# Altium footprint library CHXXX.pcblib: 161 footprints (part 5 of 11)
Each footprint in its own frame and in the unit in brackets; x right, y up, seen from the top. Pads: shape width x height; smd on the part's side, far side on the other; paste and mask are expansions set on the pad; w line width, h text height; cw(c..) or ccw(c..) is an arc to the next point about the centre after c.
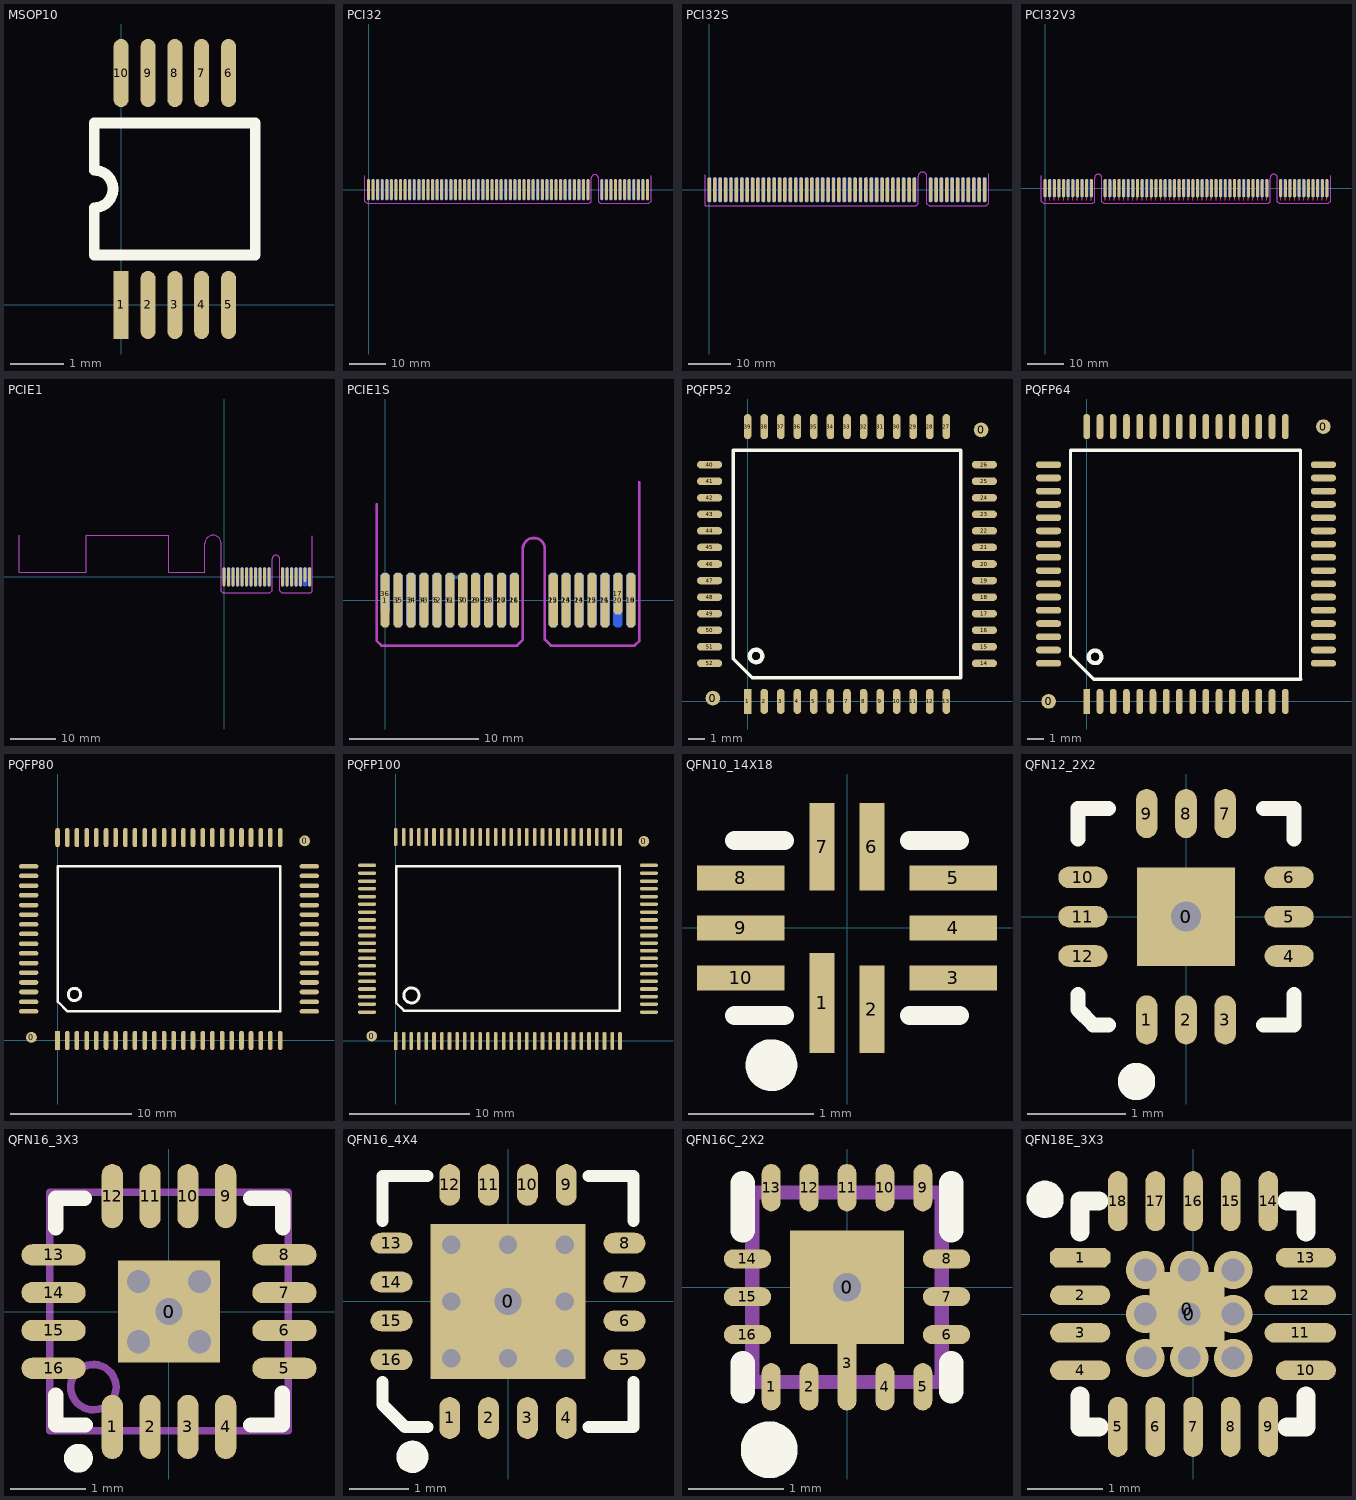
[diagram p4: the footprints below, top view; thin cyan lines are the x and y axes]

## MSOP10 [mil]
pads (10):
  rect 11x50 smd mask+2: 1(0,0)
  oval 11x50 smd mask+2: 2(19.68,0) 3(39.37,0) 4(59.06,0) 5(78.74,0) 6(78.74,170) 7(59.06,170) 8(39.37,170) 9(19.68,170) 10(0,170)
TopOverlay:
  lines w7.87: -19.8,36.65 98.32,36.65 98.32,133.35 -19.8,133.35 -19.8,98.78 cw(c-19.8,85) -19.8,71.22 -19.8,36.65

## PCI32 [mil]
pads (120):
  oct 32x230 smd: 1(0,0) 2(50,0) 3(100,0) 4(150,0) 5(200,0) 6(250,0) 7(300,0) 8(350,0) 9(400,0) 10(450,0) 11(500,0) 12(550,0) 13(600,0) 14(650,0) 15(700,0) 16(750,0) 17(800,0) 18(850,0) 19(900,0) 20(950,0) 21(1000,0) 22(1050,0) 23(1100,0) 24(1150,0) 25(1200,0) 26(1250,0) 27(1300,0) 28(1350,0) 29(1400,0) 30(1450,0) 31(1500,0) 32(1550,0) 33(1600,0) 34(1650,0) 35(1700,0) 36(1750,0) 37(1800,0) 38(1850,0) 39(1900,0) 40(1950,0) 41(2000,0) 42(2050,0) 43(2100,0) 44(2150,0) 45(2200,0) 46(2250,0) 47(2300,0) 48(2350,0) 49(2400,0) 52(2550,0) 53(2600,0) 54(2650,0) 55(2700,0) 56(2750,0) 57(2800,0) 58(2850,0) 59(2900,0) 60(2950,0) 61(3000,0) 62(3050,0)
  oct 32x230 smd far side: 63(3050,0) 64(3000,0) 65(2950,0) 66(2900,0) 67(2850,0) 68(2800,0) 69(2750,0) 70(2700,0) 71(2650,0) 72(2600,0) 73(2550,0) 76(2400,0) 77(2350,0) 78(2300,0) 79(2250,0) 80(2200,0) 81(2150,0) 82(2100,0) 83(2050,0) 84(2000,0) 85(1950,0) 86(1900,0) 87(1850,0) 88(1800,0) 89(1750,0) 90(1700,0) 91(1650,0) 92(1600,0) 93(1550,0) 94(1500,0) 95(1450,0) 96(1400,0) 97(1350,0) 98(1300,0) 99(1250,0) 100(1200,0) 101(1150,0) 102(1100,0) 103(1050,0) 104(1000,0) 105(950,0) 106(900,0) 107(850,0) 108(800,0) 109(750,0) 110(700,0) 111(650,0) 112(600,0) 113(550,0) 114(500,0) 115(450,0) 116(400,0) 117(350,0) 118(300,0) 119(250,0) 120(200,0) 121(150,0) 122(100,0) 123(50,0) 124(0,0)
TopSolder:
  rectangle: -40,-150 2435,120
  rectangle: 2515,-150 3090,120
BottomSolder:
  rectangle: 2515,-150 3090,120
  rectangle: -40,-150 2435,120
KeepOutLayer:
  lines w10: -40,150 -40,-125 -15,-150 2415,-150 2435,-130 2435,125 cw(c2475,125) 2515,125 2515,-130 2535,-150 3065,-150 3090,-125 3090,150
Mechanical1:
  lines w10: -40,150 -40,-125 -15,-150 2415,-150 2435,-130 2435,125 cw(c2475,125) 2515,125 2515,-130 2535,-150 3065,-150 3090,-125 3090,150

## PCI32S [mil]
pads (100):
  oct 32x230 smd: 11(0,0) 12(50,0) 13(100,0) 14(150,0) 15(200,0) 16(250,0) 17(300,0) 18(350,0) 19(400,0) 20(450,0) 21(500,0) 22(550,0) 23(600,0) 24(650,0) 25(700,0) 26(750,0) 27(800,0) 28(850,0) 29(900,0) 30(950,0) 31(1000,0) 32(1050,0) 33(1100,0) 34(1150,0) 35(1200,0) 36(1250,0) 37(1300,0) 38(1350,0) 39(1400,0) 40(1450,0) 41(1500,0) 42(1550,0) 43(1600,0) 44(1650,0) 45(1700,0) 46(1750,0) 47(1800,0) 48(1850,0) 49(1900,0) 52(2050,0) 53(2100,0) 54(2150,0) 55(2200,0) 56(2250,0) 57(2300,0) 58(2350,0) 59(2400,0) 60(2450,0) 61(2500,0) 62(2550,0)
  oct 32x230 smd far side: 63(2550,0) 64(2500,0) 65(2450,0) 66(2400,0) 67(2350,0) 68(2300,0) 69(2250,0) 70(2200,0) 71(2150,0) 72(2100,0) 73(2050,0) 76(1900,0) 77(1850,0) 78(1800,0) 79(1750,0) 80(1700,0) 81(1650,0) 82(1600,0) 83(1550,0) 84(1500,0) 85(1450,0) 86(1400,0) 87(1350,0) 88(1300,0) 89(1250,0) 90(1200,0) 91(1150,0) 92(1100,0) 93(1050,0) 94(1000,0) 95(950,0) 96(900,0) 97(850,0) 98(800,0) 99(750,0) 100(700,0) 101(650,0) 102(600,0) 103(550,0) 104(500,0) 105(450,0) 106(400,0) 107(350,0) 108(300,0) 109(250,0) 110(200,0) 111(150,0) 112(100,0) 113(50,0) 114(0,0)
TopSolder:
  rectangle: -40,-150 1935,120
  rectangle: 2015,-150 2590,120
BottomSolder:
  rectangle: 2015,-150 2590,120
  rectangle: -40,-150 1935,120
KeepOutLayer:
  lines w10: -40,140 -40,-150 1915,-150 1935,-130 1935,125 cw(c1975,125) 2015,125 2015,-130 2035,-150 2565,-150 2590,-125 2590,150
Mechanical1:
  lines w10: -40,140 -40,-150 1915,-150 1935,-130 1935,125 cw(c1975,125) 2015,125 2015,-130 2035,-150 2565,-150 2590,-125 2590,150

## PCI32V3 [mm]
pads (116):
  oval 0.813x5 smd: 1(0,0) 2(1.27,0) 3(2.54,0) 4(3.81,0) 5(5.08,0) 6(6.35,0) 7(7.62,0) 8(8.89,0) 9(10.16,0) 10(11.43,0) 11(12.7,0) 14(16.51,0) 15(17.78,0) 16(19.05,0) 17(20.32,0) 18(21.59,0) 19(22.86,0) 20(24.13,0) 21(25.4,0) 22(26.67,0) 23(27.94,0) 24(29.21,0) 25(30.48,0) 26(31.75,0) 27(33.02,0) 28(34.29,0) 29(35.56,0) 30(36.83,0) 31(38.1,0) 32(39.37,0) 33(40.64,0) 34(41.91,0) 35(43.18,0) 36(44.45,0) 37(45.72,0) 38(46.99,0) 39(48.26,0) 40(49.53,0) 41(50.8,0) 42(52.07,0) 43(53.34,0) 44(54.61,0) 45(55.88,0) 46(57.15,0) 47(58.42,0) 48(59.69,0) 49(60.96,0) 52(64.77,0) 53(66.04,0) 54(67.31,0) 55(68.58,0) 56(69.85,0) 57(71.12,0) 58(72.39,0) 59(73.66,0) 60(74.93,0) 61(76.2,0) 62(77.47,0)
  oval 0.813x5 smd far side: 63(77.47,0) 64(76.2,0) 65(74.93,0) 66(73.66,0) 67(72.39,0) 68(71.12,0) 69(69.85,0) 70(68.58,0) 71(67.31,0) 72(66.04,0) 73(64.77,0) 76(60.96,0) 77(59.69,0) 78(58.42,0) 79(57.15,0) 80(55.88,0) 81(54.61,0) 82(53.34,0) 83(52.07,0) 84(50.8,0) 85(49.53,0) 86(48.26,0) 87(46.99,0) 88(45.72,0) 89(44.45,0) 90(43.18,0) 91(41.91,0) 92(40.64,0) 93(39.37,0) 94(38.1,0) 95(36.83,0) 96(35.56,0) 97(34.29,0) 98(33.02,0) 99(31.75,0) 100(30.48,0) 101(29.21,0) 102(27.94,0) 103(26.67,0) 104(25.4,0) 105(24.13,0) 106(22.86,0) 107(21.59,0) 108(20.32,0) 109(19.05,0) 110(17.78,0) 111(16.51,0) 114(12.7,0) 115(11.43,0) 116(10.16,0) 117(8.89,0) 118(7.62,0) 119(6.35,0) 120(5.08,0) 121(3.81,0) 122(2.54,0) 123(1.27,0) 124(0,0)
TopLayer:
  lines w0.305: 0,-3.302 0,-2 ; 1.27,-3.302 1.27,-2 ; 2.54,-3.302 2.54,-2 ; 3.81,-3.302 3.81,-2 ; 5.08,-3.302 5.08,-2 ; 6.35,-3.302 6.35,-2 ; 7.62,-3.302 7.62,-2 ; 8.89,-3.302 8.89,-2 ; 10.16,-3.302 10.16,-2 ; 11.43,-3.302 11.43,-2 ; 12.7,-3.302 12.7,-2 ; 16.51,-3.302 16.51,-2 ; 17.78,-3.302 17.78,-2 ; 19.05,-3.302 19.05,-2 ; 20.32,-3.302 20.32,-2 ; 21.59,-3.302 21.59,-2 ; 22.86,-3.302 22.86,-2 ; 24.13,-3.302 24.13,-2 ; 25.4,-3.302 25.4,-2 ; 26.67,-3.302 26.67,-2 ; 27.94,-3.302 27.94,-2 ; 29.21,-3.302 29.21,-2 ; 30.48,-3.302 30.48,-2 ; 31.75,-3.302 31.75,-2 ; 33.02,-3.302 33.02,-2 ; 34.29,-3.302 34.29,-2 ; 35.56,-3.302 35.56,-2 ; 36.83,-3.302 36.83,-2 ; 38.1,-3.302 38.1,-2 ; 39.37,-3.302 39.37,-2 ; 40.64,-3.302 40.64,-2 ; 41.91,-3.302 41.91,-2 ; 43.18,-3.302 43.18,-2 ; 44.45,-3.302 44.45,-2 ; 45.72,-3.302 45.72,-2 ; 46.99,-3.302 46.99,-2 ; 48.26,-3.302 48.26,-2 ; 49.53,-3.302 49.53,-2 ; 50.8,-3.302 50.8,-2 ; 52.07,-3.302 52.07,-2 ; 53.34,-3.302 53.34,-2 ; 54.61,-3.302 54.61,-2 ; 55.88,-3.302 55.88,-2 ; 57.15,-3.302 57.15,-2 ; 58.42,-3.302 58.42,-2 ; 59.69,-3.302 59.69,-2 ; 60.96,-3.302 60.96,-2 ; 64.77,-3.302 64.77,-2 ; 66.04,-3.302 66.04,-2 ; 67.31,-3.302 67.31,-2 ; 68.58,-3.302 68.58,-2 ; 69.85,-3.302 69.85,-2 ; 71.12,-3.302 71.12,-2 ; 72.39,-3.302 72.39,-2 ; 73.66,-3.302 73.66,-2 ; 74.93,-3.302 74.93,-2 ; 76.2,-3.302 76.2,-2 ; 77.47,-3.302 77.47,-2
BottomLayer:
  lines w0.305: 0,-3.302 0,-2 ; 1.27,-3.302 1.27,-2 ; 2.54,-3.302 2.54,-2 ; 3.81,-3.302 3.81,-2 ; 5.08,-3.302 5.08,-2 ; 6.35,-3.302 6.35,-2 ; 7.62,-3.302 7.62,-2 ; 8.89,-3.302 8.89,-2 ; 10.16,-3.302 10.16,-2 ; 11.43,-3.302 11.43,-2 ; 12.7,-3.302 12.7,-2 ; 16.51,-3.302 16.51,-2 ; 17.78,-3.302 17.78,-2 ; 19.05,-3.302 19.05,-2 ; 20.32,-3.302 20.32,-2 ; 21.59,-3.302 21.59,-2 ; 22.86,-3.302 22.86,-2 ; 24.13,-3.302 24.13,-2 ; 25.4,-3.302 25.4,-2 ; 26.67,-3.302 26.67,-2 ; 27.94,-3.302 27.94,-2 ; 29.21,-3.302 29.21,-2 ; 30.48,-3.302 30.48,-2 ; 31.75,-3.302 31.75,-2 ; 33.02,-3.302 33.02,-2 ; 34.29,-3.302 34.29,-2 ; 35.56,-3.302 35.56,-2 ; 36.83,-3.302 36.83,-2 ; 38.1,-3.302 38.1,-2 ; 39.37,-3.302 39.37,-2 ; 40.64,-3.302 40.64,-2 ; 41.91,-3.302 41.91,-2 ; 43.18,-3.302 43.18,-2 ; 44.45,-3.302 44.45,-2 ; 45.72,-3.302 45.72,-2 ; 46.99,-3.302 46.99,-2 ; 48.26,-3.302 48.26,-2 ; 49.53,-3.302 49.53,-2 ; 50.8,-3.302 50.8,-2 ; 52.07,-3.302 52.07,-2 ; 53.34,-3.302 53.34,-2 ; 54.61,-3.302 54.61,-2 ; 55.88,-3.302 55.88,-2 ; 57.15,-3.302 57.15,-2 ; 58.42,-3.302 58.42,-2 ; 59.69,-3.302 59.69,-2 ; 60.96,-3.302 60.96,-2 ; 64.77,-3.302 64.77,-2 ; 66.04,-3.302 66.04,-2 ; 67.31,-3.302 67.31,-2 ; 68.58,-3.302 68.58,-2 ; 69.85,-3.302 69.85,-2 ; 71.12,-3.302 71.12,-2 ; 72.39,-3.302 72.39,-2 ; 73.66,-3.302 73.66,-2 ; 74.93,-3.302 74.93,-2 ; 76.2,-3.302 76.2,-2 ; 77.47,-3.302 77.47,-2
TopSolder:
  rectangle: 63.881,-4.039 78.283,2.794
  region: 61.849,2.794 15.621,2.794 15.621,-3.962 61.849,-3.962
  rectangle: -1.016,-4.064 13.386,2.769
BottomSolder:
  rectangle: 15.621,-4.267 61.849,2.794
  rectangle: 63.881,-4.115 78.257,2.692
  rectangle: -0.991,-4.089 13.386,2.718
KeepOutLayer:
  lines w0.254: -1.016,3.429 -1.016,-3.556 -0.381,-4.191 13.081,-4.191 13.589,-3.683 13.589,2.794 cw(c14.605,2.794) 15.621,2.794 15.621,-3.683 16.129,-4.191 61.341,-4.191 61.849,-3.683 61.849,2.794 cw(c62.865,2.794) 63.881,2.794 63.881,-3.683 64.389,-4.191 77.851,-4.191 78.486,-3.556 78.486,3.429
Mechanical1:
  lines w0.254: -1.016,3.429 -1.016,-3.556 -0.381,-4.191 13.081,-4.191 13.589,-3.683 13.589,2.794 cw(c14.605,2.794) 15.621,2.794 15.621,-3.683 16.129,-4.191 61.341,-4.191 61.849,-3.683 61.849,2.794 cw(c62.865,2.794) 63.881,2.794 63.881,-3.683 64.389,-4.191 77.851,-4.191 78.486,-3.556 78.486,3.429

## PCIE1 [mm]
pads (36):
  oct 0.7x4.2 smd: 1(0,0) 2(1,0) 3(2,0) 4(3,0) 5(4,0) 6(5,0) 7(6,0) 8(7,0) 9(8,0) 10(9,0) 11(10,0) 12(13,0) 13(14,0) 14(15,0) 15(16,0) 16(17,0) 18(19,0)
  oct 0.7x3.2 smd: 17(18,0.5)
  oct 0.7x4.2 smd far side: 19(19,0) 20(18,0) 21(17,0) 22(16,0) 23(15,0) 24(14,0) 25(13,0) 26(10,0) 27(9,0) 28(8,0) 29(7,0) 30(6,0) 31(5,0) 32(4,0) 33(3,0) 34(2,0) 35(1,0)
  oct 0.7x3.2 smd far side: 36(0,0.5)
KeepOutLayer:
  lines w0.2: -45.644,9.233 -45.644,0.983 -30.644,0.983 -30.644,9.233 -12.3,9.233 -12.3,0.983 -4.3,0.983 -4.3,7.414 cw(c-2.475,7.414) -0.65,7.414 -0.65,-3.149 -0.294,-3.504 ; -0.288,-3.517 10.194,-3.517 ; 10.194,-3.504 10.652,-3.047 10.652,3.988 ; 10.649,3.953 cw(c11.5,3.953) 12.351,3.953 ; 12.348,3.988 12.348,-3.045 12.806,-3.502 ; 12.808,-3.517 19.294,-3.517 ; 19.294,-3.504 19.65,-3.149 19.65,9.101
Mechanical1:
  lines w0.2: -45.644,9.233 -45.644,0.983 -30.644,0.983 -30.644,9.233 -12.3,9.233 -12.3,0.983 -4.3,0.983 -4.3,7.414 ; 10.649,3.953 10.649,-3.045 10.652,-3.047 10.188,-3.511 -0.288,-3.511 -0.65,-3.149 -0.65,7.414 ccw(c-2.475,7.414) -4.3,7.414 ; 10.652,3.988 cw(c11.5,3.953) 12.349,3.953 ; 12.351,3.953 12.351,-3.042 12.808,-3.499 19.277,-3.499 19.628,-3.149 19.628,9.079 ; -4.3,7.414 -4.3,7.414

## PCIE1S [mm]
pads (36):
  oct 0.7x4.2 smd: 1(0,0) 2(1,0) 3(2,0) 4(3,0) 5(4,0) 6(5,0) 7(6,0) 8(7,0) 9(8,0) 10(9,0) 11(10,0) 12(13,0) 13(14,0) 14(15,0) 15(16,0) 16(17,0) 18(19,0)
  oct 0.7x3.2 smd: 17(18,0.5)
  oct 0.7x4.2 smd far side: 19(19,0) 20(18,0) 21(17,0) 22(16,0) 23(15,0) 24(14,0) 25(13,0) 26(10,0) 27(9,0) 28(8,0) 29(7,0) 30(6,0) 31(5,0) 32(4,0) 33(3,0) 34(2,0) 35(1,0)
  oct 0.7x3.2 smd far side: 36(0,0.5)
BottomLayer:
  lines w0.254: 5.08,1.778 5.842,1.778
KeepOutLayer:
  lines w0.2: -0.65,7.414 -0.65,-3.149 -0.294,-3.504 ; -0.288,-3.517 10.194,-3.517 ; 10.194,-3.504 10.652,-3.047 10.652,3.988 ; 10.649,3.953 cw(c11.5,3.953) 12.351,3.953 ; 12.348,3.988 12.348,-3.045 12.821,-3.517 19.294,-3.517 ; 19.294,-3.504 19.65,-3.149 19.65,9.101
Mechanical1:
  lines w0.2: -0.65,7.414 -0.65,-3.149 -0.65,-3.155 -0.288,-3.517 10.194,-3.517 10.652,-3.06 10.652,3.953 cw(c11.5,3.953) 12.349,3.953 ; 12.348,-3.045 12.353,-3.045 12.826,-3.517 19.294,-3.517 19.65,-3.161 19.65,-3.149 19.65,9.101 ; 12.351,-3.042 12.351,3.953

## PQFP52 [mil]
pads (54):
  round 35 smd: 0(-82.68,7.87) 0(555.12,645.67)
  rect 18x60 smd: 1(0,0)
  oval 18x60 smd: 2(39.37,0) 3(78.74,0) 4(118.11,0) 5(157.48,0) 6(196.85,0) 7(236.22,0) 8(275.59,0) 9(314.96,0) 10(354.33,0) 11(393.7,0) 12(433.07,0) 13(472.44,0) 27(472.44,653.54) 28(433.07,653.54) 29(393.7,653.54) 30(354.33,653.54) 31(314.96,653.54) 32(275.59,653.54) 33(236.22,653.54) 34(196.85,653.54) 35(157.48,653.54) 36(118.11,653.54) 37(78.74,653.54) 38(39.37,653.54) 39(0,653.54)
  oval 60x18 smd: 14(562.99,90.55) 15(562.99,129.92) 16(562.99,169.29) 17(562.99,208.66) 18(562.99,248.03) 19(562.99,287.4) 20(562.99,326.77) 21(562.99,366.14) 22(562.99,405.51) 23(562.99,444.88) 24(562.99,484.25) 25(562.99,523.62) 26(562.99,562.99) 40(-90.55,562.99) 41(-90.55,523.62) 42(-90.55,484.25) 43(-90.55,444.88) 44(-90.55,405.51) 45(-90.55,366.14) 46(-90.55,326.77) 47(-90.55,287.4) 48(-90.55,248.03) 49(-90.55,208.66) 50(-90.55,169.29) 51(-90.55,129.92) 52(-90.55,90.55)
TopOverlay:
  circle w10: c20,108 r15
  lines w7.87: -34.06,101.18 -34.06,597.05 506.5,597.05 506.5,56.5 10.63,56.5 -34.06,101.18

## PQFP64 [mil]
pads (66):
  round 35 smd: 0(-90.55,0) 0(562.99,653.54)
  rect 16x60 smd: 1(0,0)
  oval 16x60 smd: 2(31.5,0) 3(62.99,0) 4(94.49,0) 5(125.98,0) 6(157.48,0) 7(188.98,0) 8(220.47,0) 9(251.97,0) 10(283.46,0) 11(314.96,0) 12(346.46,0) 13(377.95,0) 14(409.45,0) 15(440.94,0) 16(472.44,0) 33(472.44,653.54) 34(440.94,653.54) 35(409.45,653.54) 36(377.95,653.54) 37(346.46,653.54) 38(314.96,653.54) 39(283.46,653.54) 40(251.97,653.54) 41(220.47,653.54) 42(188.98,653.54) 43(157.48,653.54) 44(125.98,653.54) 45(94.49,653.54) 46(62.99,653.54) 47(31.5,653.54) 48(0,653.54)
  oval 60x16 smd: 17(562.99,90.55) 18(562.99,122.05) 19(562.99,153.54) 20(562.99,185.04) 21(562.99,216.54) 22(562.99,248.03) 23(562.99,279.53) 24(562.99,311.02) 25(562.99,342.52) 26(562.99,374.02) 27(562.99,405.51) 28(562.99,437.01) 29(562.99,468.5) 30(562.99,500) 31(562.99,531.5) 32(562.99,562.99) 49(-90.55,562.99) 50(-90.55,531.5) 51(-90.55,500) 52(-90.55,468.5) 53(-90.55,437.01) 54(-90.55,405.51) 55(-90.55,374.02) 56(-90.55,342.52) 57(-90.55,311.02) 58(-90.55,279.53) 59(-90.55,248.03) 60(-90.55,216.54) 61(-90.55,185.04) 62(-90.55,153.54) 63(-90.55,122.05) 64(-90.55,90.55)
TopOverlay:
  circle w10: c20,106 r15
  lines w7.87: -38.34,107.06 -38.34,597.65 508.78,597.65 508.78,52.53
  lines w8: -38.34,107.06 -38.05,107.06 16.47,52.53 508.78,52.53

## PQFP80 [mil]
pads (82):
  round 35 smd: 0(-85,10) 0(805,650)
  rect 15x63 smd: 1(0,0)
  oval 15x63 smd: 2(32,0) 3(63,0) 4(95,0) 5(126,0) 6(158,0) 7(189,0) 8(221,0) 9(252,0) 10(284,0) 11(315,0) 12(347,0) 13(378,0) 14(410,0) 15(441,0) 16(473,0) 17(504,0) 18(536,0) 19(567,0) 20(599,0) 21(630,0) 22(662,0) 23(693,0) 24(725,0) 41(725,661) 42(693,661) 43(662,661) 44(630,661) 45(599,661) 46(567,661) 47(536,661) 48(504,661) 49(473,661) 50(441,661) 51(410,661) 52(378,661) 53(347,661) 54(315,661) 55(284,661) 56(252,661) 57(221,661) 58(189,661) 59(158,661) 60(126,661) 61(95,661) 62(63,661) 63(32,661) 64(0,661)
  oval 63x15 smd: 25(820,95) 26(820,126) 27(820,158) 28(820,189) 29(820,221) 30(820,252) 31(820,284) 32(820,315) 33(820,347) 34(820,378) 35(820,410) 36(820,441) 37(820,473) 38(820,504) 39(820,536) 40(820,567) 65(-94,567) 66(-94,536) 67(-94,504) 68(-94,473) 69(-94,441) 70(-94,410) 71(-94,378) 72(-94,347) 73(-94,315) 74(-94,284) 75(-94,252) 76(-94,221) 77(-94,189) 78(-94,158) 79(-94,126) 80(-94,95)
TopOverlay:
  circle w10: c55,150 r20
  lines w8: 0,126 0,567 725,567 725,95 32,95 1,126

## PQFP100 [mil]
pads (102):
  round 35 smd: 0(-78.74,16.26) 0(816.74,656.74)
  rect 12x60 smd: 1(0,0)
  oct 12x60 smd: 2(26,0) 3(51,0) 4(76,0) 5(101,0) 6(126,0) 7(152,0) 8(177,0) 9(202,0) 10(227,0) 11(252,0) 12(278,0) 13(303,0) 14(329,0) 15(355,0) 16(380,0) 17(406,0) 18(431,0) 19(457,0) 20(483,0) 21(508,0) 22(534,0) 23(559,0) 24(585,0) 25(611,0) 26(636,0) 27(662,0) 28(687,0) 29(713,0) 30(738,0) 51(738,671) 52(713,671) 53(687,671) 54(662,671) 55(636,671) 56(611,671) 57(585,671) 58(559,671) 59(534,671) 60(508,671) 61(483,671) 62(457,671) 63(431,671) 64(406,671) 65(380,671) 66(355,671) 67(329,671) 68(303,671) 69(278,671) 70(252,671) 71(227,671) 72(202,671) 73(177,671) 74(152,671) 75(126,671) 76(101,671) 77(76,671) 78(51,671) 79(26,671) 80(0,671)
  oct 60x12 smd: 31(833,95) 32(833,121) 33(833,146) 34(833,171) 35(833,196) 36(833,221) 37(833,247) 38(833,272) 39(833,297) 40(833,322) 41(833,347) 42(833,373) 43(833,398) 44(833,424) 45(833,450) 46(833,475) 47(833,501) 48(833,526) 49(833,552) 50(833,578) 81(-94,578) 82(-94,552) 83(-94,526) 84(-94,501) 85(-94,475) 86(-94,450) 87(-94,424) 88(-94,398) 89(-94,373) 90(-94,347) 91(-94,322) 92(-94,297) 93(-94,272) 94(-94,247) 95(-94,221) 96(-94,196) 97(-94,171) 98(-94,146) 99(-94,121) 100(-94,95)
TopOverlay:
  circle w10: c52,150 r25
  lines w8: 2,125 27,100 737,100 737,575 2,575 2,125

## QFN10_14X18 [mm]
pads (10):
  rect 0.2x0.8 smd mask+0.051: 1(-0.2,-0.6)
  rect 0.2x0.7 smd mask+0.051: 2(0.2,-0.65) 6(0.2,0.65) 7(-0.2,0.65)
  rect 0.7x0.2 smd mask+0.051: 3(0.85,-0.4) 4(0.85,0) 5(0.85,0.4) 8(-0.85,0.4) 9(-0.85,0) 10(-0.85,-0.4)
TopOverlay:
  circle w0.254: c-0.605,-1.098 r0.08
  lines w0.152: -0.9,-0.7 -0.5,-0.7 ; -0.9,0.7 -0.5,0.7 ; 0.5,-0.7 0.9,-0.7 ; 0.5,0.7 0.9,0.7

## QFN12_2X2 [mm]
pads (14):
  rect 1x1 smd paste+0 mask+0.051: 0(0,0)
  round 0.508 hole 0.305 mask+0.102: 0(0,0)
  oval 0.22x0.5 smd mask+0.051: 1(-0.4,-1.05) 2(0,-1.05) 3(0.4,-1.05) 7(0.4,1.05) 8(0,1.05) 9(-0.4,1.05)
  oval 0.5x0.22 smd mask+0.051: 4(1.05,-0.4) 5(1.05,0) 6(1.05,0.4) 10(-1.05,0.4) 11(-1.05,0) 12(-1.05,-0.4)
TopOverlay:
  circle w0.229: c-0.504,-1.677 r0.076
  lines w0.152: -1.1,-0.789 -1.1,-0.945 -0.945,-1.1 -0.789,-1.1 ; -1.1,0.789 -1.1,1.1 -0.789,1.1 ; 0.789,-1.1 1.1,-1.1 1.1,-0.789 ; 0.789,1.1 1.1,1.1 1.1,0.789

## QFN16_3X3 [mm]
pads (18):
  rect 1.35x1.35 smd mask+0.051: 0(0,0)
  round 0.508 hole 0.356: 0(0,0)
  oval 0.28x0.85 smd mask+0.051: 1(-0.75,-1.526) 2(-0.25,-1.526) 3(0.25,-1.526) 4(0.75,-1.526) 9(0.75,1.526) 10(0.25,1.526) 11(-0.25,1.526) 12(-0.75,1.526)
  oval 0.85x0.28 smd mask+0.051: 5(1.526,-0.75) 6(1.526,-0.25) 7(1.526,0.25) 8(1.526,0.75) 13(-1.526,0.75) 14(-1.526,0.25) 15(-1.526,-0.25) 16(-1.526,-0.75)
via -0.405,-0.399 diameter 0.508 hole 0.305
via 0.405,-0.399 diameter 0.508 hole 0.305
via 0.405,0.399 diameter 0.508 hole 0.305
via -0.405,0.399 diameter 0.508 hole 0.305
TopOverlay:
  circle w0.229: c-1.198,-1.94 r0.076
  lines w0.203: -1.497,-1.108 -1.497,-1.5 -1.105,-1.5 ; -1.497,1.105 -1.497,1.5 -1.118,1.5 ; 1.079,-1.5 1.5,-1.5 1.5,-1.08 ; 1.082,1.5 1.503,1.5 1.503,1.108
Mechanical13:
  circle w0.1: c-1,-1 r0.3
  lines w0.1: -1.575,-1.575 -1.575,1.575 1.575,1.575 1.575,-1.575 -1.575,-1.575
3D body: height 0.25, standoff 0, extent -1.521,-1.519 1.521,1.523

## QFN16_4X4 [mm]
pads (18):
  rect 2.6x2.6 smd mask+0.051: 0(0,0)
  round 0.762 hole 0.457: 0(0,0)
  oval 0.35x0.7 smd mask+0.051: 1(-0.975,-1.95) 2(-0.325,-1.95) 3(0.325,-1.95) 4(0.975,-1.95) 9(0.975,1.95) 10(0.325,1.95) 11(-0.325,1.95) 12(-0.975,1.95)
  oval 0.7x0.35 smd mask+0.051: 5(1.95,-0.975) 6(1.95,-0.325) 7(1.95,0.325) 8(1.95,0.975) 13(-1.95,0.975) 14(-1.95,0.325) 15(-1.95,-0.325) 16(-1.95,-0.975)
via -0.95,-0.95 diameter 0.61 hole 0.305
via 0.95,-0.95 diameter 0.61 hole 0.305
via 0.95,0.95 diameter 0.61 hole 0.305
via -0.95,0.95 diameter 0.61 hole 0.305
via 0,0.95 diameter 0.61 hole 0.305
via -0.95,0 diameter 0.61 hole 0.305
via 0,-0.95 diameter 0.61 hole 0.305
via 0.95,0 diameter 0.61 hole 0.305
TopOverlay:
  circle w0.3: c-1.6,-2.6 r0.12
  lines w0.203: -2.1,-1.35 -2.1,-1.725 -1.725,-2.1 -1.35,-2.1 ; -2.1,1.35 -2.1,2.1 -1.35,2.1 ; 1.35,-2.1 2.1,-2.1 2.1,-1.35 ; 1.35,2.1 2.1,2.1 2.1,1.35

## QFN16C_2X2 [mm]
pads (18):
  rect 1.2x1.2 smd mask+0.051: 0(0,0)
  round 0.5 hole 0.3 mask+0.051: 0(0,0)
  oval 0.2x0.5 smd mask+0.051: 1(-0.8,-1.05) 2(-0.4,-1.05) 4(0.4,-1.05) 5(0.8,-1.05) 9(0.8,1.05) 10(0.4,1.05) 11(0,1.05) 12(-0.4,1.05) 13(-0.8,1.05)
  oval 0.2x1 smd mask+0.051: 3(0,-0.8)
  oval 0.5x0.2 smd mask+0.051: 6(1.05,-0.5) 7(1.05,-0.1) 8(1.05,0.3) 14(-1.05,0.3) 15(-1.05,-0.1) 16(-1.05,-0.5)
TopOverlay:
  circle w0.3: c-0.821,-1.715 r0.15
  lines w0.254: -1.1,-1.1 -1.1,-0.8 ; -1.1,0.6 -1.1,1.1 ; 1.1,-1.1 1.1,-0.8 ; 1.1,0.6 1.1,1.1
Mechanical15:
  lines w0.15: -1,-1 1,-1 1,1 -1,1 -1,-1

## QFN18E_3X3 [mm]
height 1.3
pads (20):
  rect 1x1 smd mask+0.051: 0(-0.08,0.06)
  round 0.508 hole 0.305 mask+0.051: 0(-0.051,0)
  oct 0.8x0.26 smd mask+0.051: 1(-1.5,0.75)
  oval 0.8x0.26 smd mask+0.051: 2(-1.5,0.25) 3(-1.5,-0.25) 4(-1.5,-0.75) 10(1.5,-0.75) 13(1.5,0.75)
  oval 0.26x0.8 smd mask+0.051: 5(-1,-1.5) 6(-0.5,-1.5) 7(0,-1.5) 8(0.5,-1.5) 9(1,-1.5) 14(1,1.5) 15(0.5,1.5) 16(0,1.5) 17(-0.5,1.5) 18(-1,1.5)
  oval 0.95x0.26 smd mask+0.051: 11(1.425,-0.25) 12(1.425,0.25)
via -0.051,0.584 diameter 0.508 hole 0.305
via -0.635,0 diameter 0.508 hole 0.305
via -0.635,0.584 diameter 0.508 hole 0.305
via 0.533,0.584 diameter 0.508 hole 0.305
via 0.533,0 diameter 0.508 hole 0.305
via 0.533,-0.584 diameter 0.508 hole 0.305
via -0.051,-0.584 diameter 0.508 hole 0.305
via -0.635,-0.584 diameter 0.508 hole 0.305
TopOverlay:
  circle w0.254: c-1.966,1.525 r0.121
  lines w0.254: -1.5,-1.092 -1.5,-1.5 -1.251,-1.5 ; -1.5,1.092 -1.5,1.5 -1.251,1.5 ; 1.251,-1.5 1.5,-1.5 1.5,-1.092 ; 1.251,1.5 1.5,1.5 1.5,1.092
